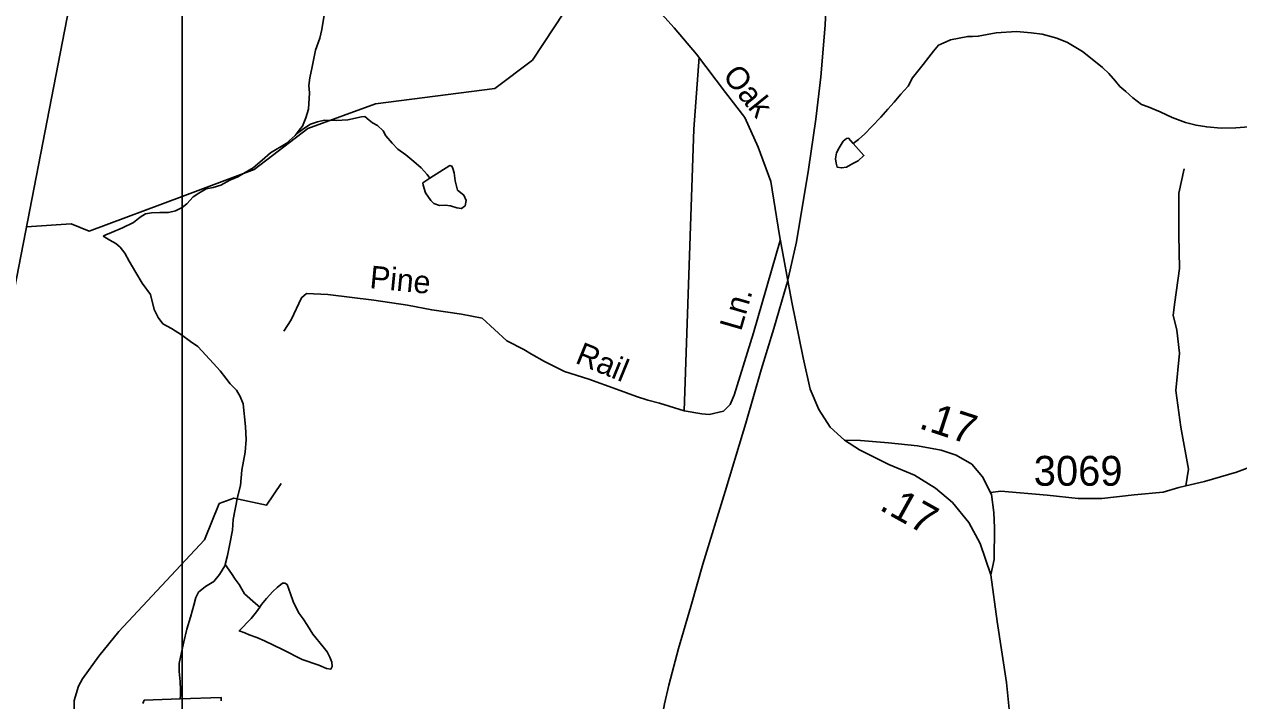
# Model space of a CAD drawing. Extents: x 2001466 to 2224147, y 644118 to 847247.
# Drawn here: x 2019811 to 2024898, y 738601 to 741433 of the extents above; entities that cross this region are included whole.
import ezdxf

# ---------------------------------------------------------------- set-up
doc = ezdxf.new("R2010")
doc.units = 0
for name, color, linetype in [('Exist Boundary Political CountyLine', 7, 'Continuous'), ('Exist Hydrographic Misc Water Feature', 7, 'Continuous'), ('Exist Railroad Mainline', 7, 'Continuous'), ('Exist Road Non-System Type 51', 7, 'Continuous'), ('Exist Road Non-System Type 51 Label', 7, 'Continuous'), ('Exist Road Secondary Mileage Hundredths English Label', 7, 'Continuous'), ('Exist Road Secondary Type 51 Attributed', 7, 'Continuous'), ('Exist Road Secondary Type 51 Label', 7, 'Continuous'), ('Exist Road Secondary Type 51 Number Label', 7, 'Continuous'), ('Map Preparation Inset Cut Line', 7, 'Continuous')]:
    doc.layers.add(name, color=color, linetype=linetype)

msp = doc.modelspace()

# ---------------------------------------------------------------- linework, layer by layer
at = {"layer": 'Exist Boundary Political CountyLine'}
msp.add_lwpolyline([(2006817.6, 695750.4), (2007499.4, 697710.6), (2010412.6, 706844.6), (2011918.3, 711705.5), (2013748.8, 717730), (2014941.8, 722041.3), (2015284.7, 723238.9), (2015749.8, 724659.3), (2016152.8, 726117.8), (2016501.7, 727373.6), (2016860.6, 728619.5), (2017411.9, 730567.4), (2017756.8, 731851.4), (2018083.6, 732956.8), (2018350.2, 733869.6), (2018833.4, 735584.8), (2018918.2, 735898.3), (2019734.3, 740137.7), (2020502.6, 744108.1), (2021805.5, 746807.9), (2022821.6, 749625), (2023527, 751602.5)], dxfattribs=at)
at = {"layer": 'Exist Hydrographic Misc Water Feature'}
for points in [[(2020472.9, 740711.9), (2020774.3, 740824.3), (2020999.3, 740996.9), (2021282.3, 741099.4), (2021782.4, 741164.6), (2021940.3, 741282.9), (2022340.3, 741891.6), (2022356.3, 741956.9), (2022440.4, 742106), (2022539.4, 742474.8), (2022489.4, 743109.1), (2022464.4, 743165.3), (2022472.4, 743365.4)], [(2021080.9, 741530.9), (2021075.4, 741503.1), (2021065.3, 741462.3), (2021057.5, 741410.8), (2021049.3, 741374.8), (2021031.5, 741324.3), (2021017.5, 741254.9), (2021007.7, 741208.4), (2021003.6, 741176.4), (2021005.6, 741146.1), (2021001.7, 741078.1), (2020990.1, 741040.6), (2020975.9, 741006.4), (2020967.9, 740996.7), (2020950.7, 740973.5), (2020946.4, 740967.6)], [(2023282.7, 740933.9), (2023306.1, 740950.6), (2023331.7, 740974.8), (2023361.5, 741005.3), (2023399.4, 741043.9), (2023428.9, 741077.8), (2023454.8, 741107.5), (2023482.7, 741139.8), (2023514.2, 741174.4), (2023532.3, 741208.5), (2023553.8, 741236.8), (2023575.8, 741265.1), (2023599.5, 741294.9), (2023619.2, 741320.7), (2023641.2, 741344.9), (2023673.2, 741359.8), (2023691, 741367.7), (2023763, 741381.8), (2023783.1, 741382.2), (2023807.1, 741382.6), (2023882.7, 741396.6), (2023966.8, 741403.1), (2024029.1, 741397.7), (2024075.1, 741391.8), (2024137, 741375), (2024181.3, 741356.9), (2024243.6, 741319.5), (2024297.7, 741275.7), (2024328.1, 741252.2), (2024354.1, 741226.2), (2024382.6, 741194.4), (2024400.7, 741172.7), (2024424.9, 741150.9), (2024455, 741124.9), (2024491.3, 741097.1), (2024519.4, 741087.4), (2024569.2, 741066), (2024619.7, 741042), (2024675.7, 741022), (2024719.9, 741010.3), (2024764, 741002.9), (2024824.1, 740997.6), (2024886, 740999.6), (2024940, 741004.2)], [(2021237.6, 741046.2), (2021223.8, 741044.8), (2021166, 741032.9), (2021118, 741030.6), (2021068, 741030.8), (2021039.9, 741024.8), (2021009.9, 741014.7), (2020981.9, 740996.5), (2020950.7, 740973.5), (2020946.4, 740967.6)], [(2021237.6, 741046.2), (2021255.8, 741031), (2021269.9, 741020.9), (2021290, 741009), (2021314, 740987.2), (2021325.9, 740966.5), (2021352.2, 740934.8), (2021376.2, 740910.5), (2021410, 740886.8), (2021442.2, 740859.1), (2021474.2, 740831.3), (2021498.2, 740804.6), (2021510.3, 740788)], [(2020946.4, 740967.6), (2020908, 740934), (2020842.2, 740894.3), (2020808.2, 740863.8), (2020770.2, 740831.8), (2020736.4, 740812), (2020706.3, 740793.7), (2020672.4, 740779.7), (2020634.3, 740759.9), (2020602.3, 740749.9), (2020572.6, 740743.9), (2020542.4, 740725.7), (2020518.4, 740709.8), (2020492.4, 740681.6), (2020472.5, 740665.6), (2020444.4, 740651.4), (2020414.7, 740645.5), (2020378.6, 740645.4), (2020344.5, 740643.7), (2020318.5, 740639.2), (2020296.8, 740625.7), (2020268.7, 740603.3), (2020222.7, 740581.3), (2020176.8, 740560.9), (2020153, 740550.7), (2020141.5, 740545.2)], [(2023282.7, 740933.9), (2023263.7, 740955.7), (2023255.7, 740954.9), (2023241.7, 740942.9), (2023223.9, 740915.4), (2023213.8, 740895.1), (2023209.7, 740868.9), (2023212, 740850.9), (2023215.9, 740835.2), (2023233.7, 740831.5), (2023255.9, 740835.2), (2023281.9, 740849.4), (2023303.9, 740861.3), (2023327.9, 740883.7), (2023282.7, 740933.9)], [(2021510.3, 740788), (2021480.3, 740768.9), (2021482.4, 740759.1), (2021492.4, 740726.9), (2021514.2, 740695.2), (2021526.3, 740682.7), (2021550.7, 740674.8), (2021574.7, 740675.1), (2021596.4, 740673), (2021622.6, 740665.1), (2021642.5, 740661.4), (2021658.3, 740673.4), (2021662.4, 740695.5), (2021652.4, 740717), (2021626.3, 740738.9), (2021616.3, 740776.8), (2021612.2, 740811.3), (2021606.2, 740829.5), (2021602.1, 740839.4), (2021594.1, 740841.2), (2021510.3, 740788)], [(2019820.9, 740585), (2020007.4, 740597.2), (2020082.3, 740566.2), (2020472.9, 740711.9)], [(2020141.5, 740545.2), (2020168.8, 740529.1), (2020194.9, 740515.5), (2020212.9, 740499.5), (2020233, 740475.3), (2020251, 740441.3), (2020278.9, 740393.1), (2020305.2, 740349.2), (2020339.2, 740301.6), (2020355.4, 740239), (2020371.4, 740205), (2020391.5, 740179.2), (2020427.4, 740159.6), (2020469.4, 740133.3), (2020507.6, 740105.5), (2020537.5, 740083.5), (2020603.5, 740013.3), (2020631.6, 739981.5), (2020655.8, 739951.5), (2020673.7, 739927.3), (2020699.7, 739901.4), (2020715.7, 739874), (2020727.8, 739843.4), (2020738, 739749.6), (2020740.3, 739693.9), (2020736, 739641.5), (2020722.3, 739565.5), (2020716.3, 739501.6), (2020704.4, 739453.4), (2020686.6, 739359.5), (2020682.7, 739315.2), (2020672.8, 739257.2), (2020662.8, 739209), (2020652.1, 739170.7)], [(2020652.1, 739170.7), (2020650.9, 739165), (2020629, 739129.3), (2020605, 739099.5), (2020570.9, 739078.9), (2020541.2, 739054.8), (2020529.3, 739032.9), (2020521.1, 739001.1), (2020507.2, 738951.3), (2020491.6, 738900.8), (2020479.3, 738846.9), (2020469.4, 738802.9), (2020459.6, 738757.1), (2020459.8, 738722.6), (2020463.7, 738680.7), (2020465.7, 738647), (2020465.7, 738624.9), (2020463.7, 738608.5)], [(2020652.1, 739170.7), (2020678.8, 739133.2), (2020694.8, 739109.9), (2020711, 739087.5), (2020733.9, 739048.4), (2020779.1, 739007.3), (2020797.5, 738992.9)], [(2020797.5, 738992.9), (2020804.9, 739003.5), (2020825.2, 739029.3), (2020852.9, 739057.5), (2020870.9, 739075.2), (2020893.1, 739093.6), (2020902.9, 739093.4), (2020913, 739087.4), (2020926.9, 739047.8), (2020937.1, 739015.6), (2020951.1, 738987.4), (2020963.2, 738965.8), (2020979.2, 738943.4), (2020997.2, 738915.9), (2021019.2, 738879.3), (2021063.3, 738826), (2021079.3, 738806), (2021091.6, 738783.5), (2021099.6, 738762.1), (2021101.4, 738744), (2021095.4, 738733.4), (2021077.4, 738735.5), (2021045.4, 738749.2), (2020975.5, 738773.6), (2020893.3, 738815.5), (2020855.1, 738833.5), (2020817.4, 738851.5), (2020785.4, 738865.3), (2020753.4, 738877.4), (2020735.4, 738885.1), (2020711.4, 738893), (2020761.2, 738945.3), (2020783.2, 738973.6), (2020797.5, 738992.9)], [(2020463.7, 738608.5), (2020313.8, 738602.6), (2020307.8, 738588.7)], [(2020635.9, 738600.9), (2020635.7, 738606.7), (2020635.7, 738614.8), (2020463.7, 738608.5)]]:
    msp.add_lwpolyline(points, dxfattribs=at)
at = {"layer": 'Exist Railroad Mainline'}
for points in [[(2023055.2, 744069.5), (2023066.1, 744034.2), (2023086, 743950.2), (2023141.5, 743718), (2023182.9, 743505.9), (2023206.5, 743356), (2023220.1, 743212), (2023229.7, 743051.9), (2023231.3, 742858.1), (2023224.7, 742644.2), (2023210, 742362.3), (2023197.3, 742084.5), (2023180.5, 741762.6), (2023165.7, 741428.7), (2023147.1, 741212.9), (2023126.6, 741035.1), (2023096.2, 740825.3), (2023045.3, 740521.5), (2023012.9, 740373.5), (2023004.7, 740345.6)], [(2023004.7, 740345.6), (2022950.3, 740159.8), (2022898, 739986), (2022832.9, 739762.9), (2022823.4, 739730.3), (2022746.8, 739476.5), (2022653.9, 739172.9), (2022603.5, 738995.1), (2022551.1, 738819.4), (2022510.6, 738665.4), (2022492.4, 738587.6), (2022474.1, 738487.5), (2022457.9, 738359.7), (2022445.6, 738245.7), (2022435.3, 738105.9), (2022426.9, 737959.8), (2022428.2, 737760), (2022436.1, 737636), (2022443.8, 737540.1), (2022459.4, 737415.9), (2022483, 737268), (2022510.7, 737086.1), (2022561.7, 736766), (2022606.9, 736481.3)]]:
    msp.add_lwpolyline(points, dxfattribs=at)
at = {"layer": 'Exist Road Non-System Type 51'}
for points in [[(2022575.3, 739814.4), (2022616.3, 740993.5), (2022638.1, 741295)], [(2023858.6, 739473.1), (2023901.2, 739478.8), (2024096.3, 739461), (2024226.2, 739448), (2024325.2, 739448), (2024460.1, 739462.4), (2024581.6, 739473.7), (2024646.8, 739493.9), (2024676, 739500.7), (2024687.3, 739570.4), (2024655.8, 739746), (2024635.2, 739899.5), (2024650.8, 740055.4), (2024639.1, 740152.9), (2024623.5, 740215.3), (2024631.3, 740269.9), (2024650.8, 740410.3), (2024646.9, 740550.7), (2024646.9, 740726.2), (2024670.3, 740827.5)], [(2022739.4, 739813.7), (2022768, 739840.7), (2022784.3, 739879.5), (2022866, 740141), (2022977.8, 740527.9)], [(2020898.5, 740148.3), (2020928.7, 740196.1), (2020972.8, 740288), (2020992.9, 740306), (2021082.9, 740301.7), (2021274.8, 740277.2), (2021416.1, 740257.5), (2021518.2, 740237.1), (2021642.8, 740218.7), (2021728.5, 740202.4), (2021832.2, 740107.8), (2021904.2, 740071.5), (2021936, 740051.5), (2021990, 740021.4), (2022074, 739979.3), (2022175.8, 739946.5), (2022292.2, 739905.6), (2022375.9, 739875), (2022422.9, 739858.6), (2022471.9, 739846.4), (2022512.7, 739834.1), (2022575.3, 739814.4)], [(2022575.3, 739814.4), (2022649.5, 739801.4), (2022680.2, 739799.4), (2022739.4, 739813.7)], [(2024676, 739500.7), (2024754.8, 739518.7), (2024888.4, 739557.9), (2025016.4, 739605.5), (2025092.1, 739633.4)], [(2020005.1, 738196.5), (2020010, 738287.2), (2020027.5, 738398.3), (2020020.5, 738541.9), (2020020.5, 738601.5), (2020038, 738661.1), (2020055.5, 738692.6), (2020123.2, 738786.8), (2020207.5, 738890.5), (2020566.5, 739274), (2020627.5, 739426.5), (2020688.5, 739449.4), (2020825.7, 739418.9), (2020886.6, 739510.4)]]:
    msp.add_lwpolyline(points, dxfattribs=at)
at = {"layer": 'Exist Road Secondary Type 51 Attributed'}
for points in [[(2023246.5, 739691.1), (2023186.4, 739746.2), (2023139.7, 739820.3), (2023102.7, 739905.7), (2023073.8, 740036.1), (2023025.9, 740269.6), (2022974.4, 740548.9), (2022937.8, 740775.2), (2022884.7, 740918.5), (2022830, 741042.5), (2022747.9, 741147.1), (2022626.8, 741308.2), (2022533.5, 741417.7), (2022428.1, 741534.4)], [(2023859.6, 739128.3), (2023815.7, 739259.6), (2023767.5, 739347.3), (2023699.1, 739430.2), (2023628.3, 739491.4), (2023539.8, 739544.6), (2023432, 739589.7), (2023310.1, 739650.8), (2023246.5, 739691.1)], [(2023246.5, 739691.1), (2023314.3, 739690.7), (2023431, 739681), (2023552.1, 739668.6), (2023651.2, 739649.2), (2023714, 739629.1), (2023780.7, 739591.3)], [(2023780.7, 739591.3), (2023825, 739538.1), (2023862.8, 739464.9), (2023872.9, 739389.2), (2023875.3, 739324), (2023874.5, 739191.9), (2023859.6, 739128.3)], [(2023978.9, 737064.8), (2023961.8, 737147.7), (2023937.6, 737427.9), (2023932.8, 737627.6), (2023935.6, 737824), (2023940.4, 738121.9), (2023944.9, 738359.4), (2023937.6, 738551.9), (2023924.8, 738677.5), (2023885.7, 738931.9), (2023859.6, 739128.3)]]:
    msp.add_lwpolyline(points, dxfattribs=at)
at = {"layer": 'Map Preparation Inset Cut Line'}
for p, q in [((2020472.9, 740711.9), (2020472.9, 743977.7)), ((2020472.9, 737706.1), (2020472.9, 740711.9))]:
    msp.add_line(p, q, dxfattribs=at)

# ---------------------------------------------------------------- texts
at = {"layer": 'Exist Road Non-System Type 51 Label'}
for s, rotation, p in [('Pine', 354.4311, (2021255.3, 740328.5)), ('Ln.', 73.8655, (2022813.5, 740144.8)), ('Rail', 337.7464, (2022114.6, 740016.6))]:
    msp.add_text(s, height=95, rotation=rotation, dxfattribs=at).set_placement(p)
at = {"layer": 'Exist Road Secondary Mileage Hundredths English Label'}
for rotation, p in [(341.9031, (2023553.9, 739743.1)), (330.9354, (2023388.2, 739403.1))]:
    msp.add_text('.17', height=125, rotation=rotation, dxfattribs=at).set_placement(p)
at = {"layer": 'Exist Road Secondary Type 51 Label'}
msp.add_text('Oak', height=95, rotation=308.8732, dxfattribs=at).set_placement((2022732.8, 741215.7))
at = {"layer": 'Exist Road Secondary Type 51 Number Label'}
msp.add_text('3069', height=125, dxfattribs=at).set_placement((2024039.7, 739500.9))

doc.saveas('drawing.dxf')
